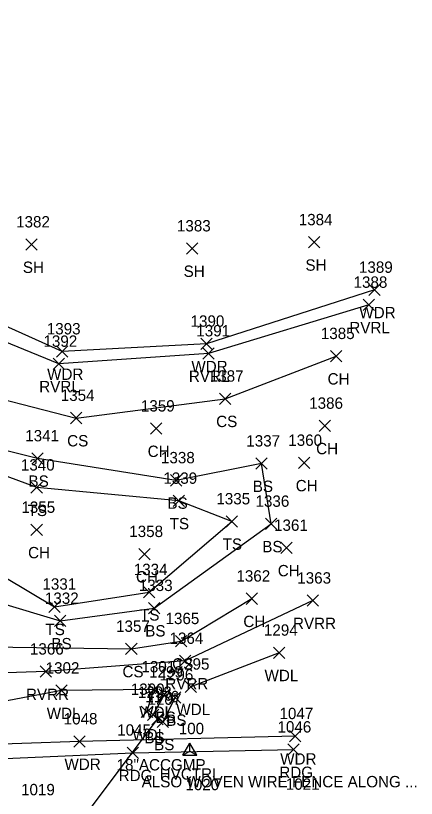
# Model space of a CAD drawing. Extents: x 1621633 to 1624015, y 417863 to 420979.
# Drawn here: x 1622271 to 1622341.5, y 418146.1 to 418283.9 of the extents above; entities that cross this region are included whole.
import ezdxf

# ---------------------------------------------------------------- set-up
doc = ezdxf.new("R2010")
doc.units = 0
for name, color, linetype in [('C_A', 7, 'Continuous'), ('C_I', 7, 'Continuous'), ('CPSM', 7, 'Continuous'), ('D_A', 7, 'Continuous'), ('D_C', 7, 'Continuous'), ('D_I', 7, 'Continuous'), ('D_TIC', 7, 'Continuous'), ('DCP', 7, 'Continuous'), ('L_A', 7, 'Continuous'), ('L_C', 7, 'Continuous'), ('L_I', 7, 'Continuous'), ('L_TIC', 7, 'Continuous'), ('LAWA', 7, 'Continuous'), ('LAWE', 7, 'Continuous'), ('LELB', 7, 'Continuous'), ('P_A', 7, 'Continuous'), ('P_I', 7, 'Continuous'), ('P_TIC', 7, 'Continuous'), ('PEU', 7, 'Continuous')]:
    doc.layers.add(name, color=color, linetype=linetype)

msp = doc.modelspace()

# ---------------------------------------------------------------- linework, layer by layer
at = {"layer": 'CPSM'}
for p, q in [((1622300.42, 418153.71), (1622301.67, 418155.87)), ((1622302.92, 418153.71), (1622301.67, 418155.87)), ((1622301.67, 418154.43), (1622301.67, 418155.87)), ((1622300.42, 418153.71), (1622301.67, 418154.43)), ((1622300.42, 418153.71), (1622302.92, 418153.71)), ((1622301.67, 418154.43), (1622301.67, 418154.43)), ((1622301.67, 418154.43), (1622302.92, 418153.71))]:
    msp.add_line(p, q, dxfattribs=at)
at = {"layer": 'D_TIC'}
for points in [[(1622294.99, 418159.05), (1622296.99, 418161.05)], [(1622296.99, 418159.05), (1622294.99, 418161.05)]]:
    msp.add_lwpolyline(points, dxfattribs=at)
at = {"layer": 'DCP'}
msp.add_lwpolyline([(1622271.54, 418127.58), (1622295.99, 418160.05)], dxfattribs=at)
at = {"layer": 'L_TIC'}
for points in [[(1622272.78, 418242.6), (1622274.78, 418244.6)], [(1622274.78, 418242.6), (1622272.78, 418244.6)], [(1622322.52, 418242.99), (1622324.52, 418244.99)], [(1622324.52, 418242.99), (1622322.52, 418244.99)], [(1622301.08, 418241.9), (1622303.08, 418243.9)], [(1622303.08, 418241.9), (1622301.08, 418243.9)], [(1622333.14, 418234.62), (1622335.14, 418236.62)], [(1622335.14, 418234.62), (1622333.14, 418236.62)], [(1622332.17, 418231.98), (1622334.17, 418233.98)], [(1622334.17, 418231.98), (1622332.17, 418233.98)], [(1622303.57, 418225.13), (1622305.57, 418227.13)], [(1622305.57, 418225.13), (1622303.57, 418227.13)], [(1622278.17, 418223.78), (1622280.17, 418225.78)], [(1622280.17, 418223.78), (1622278.17, 418225.78)], [(1622303.92, 418223.43), (1622305.92, 418225.43)], [(1622305.92, 418223.43), (1622303.92, 418225.43)], [(1622326.42, 418222.96), (1622328.42, 418224.96)], [(1622328.42, 418222.96), (1622326.42, 418224.96)], [(1622277.58, 418221.6), (1622279.58, 418223.6)], [(1622279.58, 418221.6), (1622277.58, 418223.6)], [(1622306.86, 418215.47), (1622308.86, 418217.47)], [(1622308.86, 418215.47), (1622306.86, 418217.47)], [(1622280.63, 418212.07), (1622282.63, 418214.07)], [(1622282.63, 418212.07), (1622280.63, 418214.07)], [(1622294.75, 418210.21), (1622296.75, 418212.21)], [(1622296.75, 418210.21), (1622294.75, 418212.21)], [(1622324.41, 418210.69), (1622326.41, 418212.69)], [(1622326.41, 418210.69), (1622324.41, 418212.69)], [(1622273.82, 418204.96), (1622275.82, 418206.96)], [(1622275.82, 418204.96), (1622273.82, 418206.96)], [(1622313.3, 418204.05), (1622315.3, 418206.05)], [(1622315.3, 418204.05), (1622313.3, 418206.05)], [(1622320.81, 418204.17), (1622322.81, 418206.17)], [(1622322.81, 418204.17), (1622320.81, 418206.17)], [(1622273.7, 418199.82), (1622275.7, 418201.82)], [(1622275.7, 418199.82), (1622273.7, 418201.82)], [(1622298.28, 418201.1), (1622300.28, 418203.1)], [(1622300.28, 418201.1), (1622298.28, 418203.1)], [(1622298.7, 418197.49), (1622300.7, 418199.49)], [(1622300.7, 418197.49), (1622298.7, 418199.49)], [(1622308.03, 418193.87), (1622310.03, 418195.87)], [(1622310.03, 418193.87), (1622308.03, 418195.87)], [(1622314.97, 418193.44), (1622316.97, 418195.44)], [(1622316.97, 418193.44), (1622314.97, 418195.44)], [(1622273.7, 418192.38), (1622275.7, 418194.38)], [(1622275.7, 418192.38), (1622273.7, 418194.38)], [(1622317.65, 418189.21), (1622319.65, 418191.21)], [(1622319.65, 418189.21), (1622317.65, 418191.21)], [(1622292.69, 418188.12), (1622294.69, 418190.12)], [(1622294.69, 418188.12), (1622292.69, 418190.12)], [(1622293.48, 418181.42), (1622295.48, 418183.42)], [(1622295.48, 418181.42), (1622293.48, 418183.42)], [(1622311.6, 418180.28), (1622313.6, 418182.28)], [(1622313.6, 418180.28), (1622311.6, 418182.28)], [(1622322.31, 418179.93), (1622324.31, 418181.93)], [(1622324.31, 418179.93), (1622322.31, 418181.93)], [(1622276.84, 418178.86), (1622278.84, 418180.86)], [(1622278.84, 418178.86), (1622276.84, 418180.86)], [(1622294.37, 418178.62), (1622296.37, 418180.62)], [(1622296.37, 418178.62), (1622294.37, 418180.62)], [(1622277.85, 418176.36), (1622279.85, 418178.36)], [(1622279.85, 418176.36), (1622277.85, 418178.36)], [(1622299.12, 418172.8), (1622301.12, 418174.8)], [(1622301.12, 418172.8), (1622299.12, 418174.8)], [(1622290.36, 418171.44), (1622292.36, 418173.44)], [(1622292.36, 418171.44), (1622290.36, 418173.44)], [(1622316.39, 418170.76), (1622318.39, 418172.76)], [(1622318.39, 418170.76), (1622316.39, 418172.76)], [(1622299.82, 418169.32), (1622301.82, 418171.32)], [(1622301.82, 418169.32), (1622299.82, 418171.32)], [(1622275.31, 418167.44), (1622277.31, 418169.44)], [(1622277.31, 418167.44), (1622275.31, 418169.44)], [(1622278.05, 418164.1), (1622280.05, 418166.1)], [(1622280.05, 418164.1), (1622278.05, 418166.1)], [(1622294.35, 418164.31), (1622296.35, 418166.31)], [(1622296.35, 418164.31), (1622294.35, 418166.31)], [(1622300.86, 418164.79), (1622302.86, 418166.79)], [(1622302.86, 418164.79), (1622300.86, 418166.79)], [(1622296.19, 418163.4), (1622298.19, 418165.4)], [(1622298.19, 418163.4), (1622296.19, 418165.4)], [(1622298.06, 418162.89), (1622300.06, 418164.89)], [(1622300.06, 418162.89), (1622298.06, 418164.89)], [(1622293.12, 418160.35), (1622295.12, 418162.35)], [(1622295.12, 418160.35), (1622293.12, 418162.35)], [(1622294.23, 418159.82), (1622296.23, 418161.82)], [(1622296.23, 418159.82), (1622294.23, 418161.82)], [(1622295.93, 418158.61), (1622297.93, 418160.61)], [(1622297.93, 418158.61), (1622295.93, 418160.61)], [(1622319.21, 418156.08), (1622321.21, 418158.08)], [(1622321.21, 418156.08), (1622319.21, 418158.08)], [(1622281.22, 418155.15), (1622283.22, 418157.15)], [(1622283.22, 418155.15), (1622281.22, 418157.15)]]:
    msp.add_lwpolyline(points, dxfattribs=at)
at = {"layer": 'LAWA'}
for points in [[(1622334.14, 418235.62), (1622304.57, 418226.13), (1622279.17, 418224.78), (1622252.77, 418236.61), (1622231.24, 418254.76), (1622207.28, 418260.97), (1622182.84, 418269.19), (1622160.31, 418273.27), (1622129.81, 418281.16), (1622108.44, 418283.87), (1622096.55, 418277.43), (1622071.98, 418274.52), (1622045.71, 418270.54), (1622021.3, 418265.82)], [(1622320.21, 418157.08), (1622282.22, 418156.15), (1622251.71, 418155.08), (1622223.6, 418155.09), (1622209.11, 418155.31), (1622180.88, 418152.89), (1622152.12, 418150.87), (1622117.37, 418144.74), (1622094.14, 418141.69), (1622062.96, 418134.28), (1622030.01, 418125.89), (1622002.09, 418113.22), (1622001.94, 418118.19), (1622004.41, 418142.61), (1621992.55, 418166.21), (1621982.92, 418190.96), (1621974.22, 418213.57), (1621987.21, 418225.09), (1622016.71, 418238.58), (1622052.18, 418242.59)], [(1622294.12, 418161.35), (1622295.35, 418165.31), (1622279.05, 418165.1), (1622262.62, 418162.03), (1622241.27, 418162.89), (1622220.84, 418170.43), (1622210.97, 418182.32), (1622187.59, 418203.03), (1622170.53, 418217.1), (1622143.74, 418224.16), (1622117.62, 418234.62), (1622098.7, 418232.3), (1622072.64, 418230.63)], [(1622317.39, 418171.76), (1622301.86, 418165.79)]]:
    msp.add_lwpolyline(points, dxfattribs=at)
at = {"layer": 'LAWE'}
for points in [[(1622333.17, 418232.98), (1622304.92, 418224.43), (1622278.58, 418222.6), (1622250.59, 418234.06), (1622231.09, 418250.9), (1622207.09, 418257.63), (1622185.14, 418265.61), (1622157.85, 418271.29), (1622128.42, 418279.11), (1622109.18, 418281.03), (1622103.42, 418276.53), (1622081.07, 418269.59), (1622054.89, 418266.85), (1622024.68, 418262.78), (1621999.35, 418261.34), (1621980.1, 418259.35), (1621959.54, 418247.53), (1621949.11, 418230.91), (1621945.67, 418206.62), (1621950.84, 418182.3), (1621958.69, 418157.04), (1621962.92, 418133.77), (1621970.23, 418110.89)], [(1622323.31, 418180.93), (1622300.82, 418170.32), (1622276.31, 418168.44), (1622241.72, 418167.29), (1622221.82, 418173.51), (1622205.88, 418194.82), (1622185.97, 418220.63), (1622162.23, 418235.42), (1622129.82, 418241.7), (1622106.38, 418246.35), (1622101.43, 418250.25), (1622073.09, 418248.58), (1622043.82, 418244.16), (1622014.93, 418241.31), (1621989.87, 418234.25), (1621972.68, 418220.99), (1621964.49, 418204.33), (1621969.88, 418176.14), (1621978.91, 418154.62), (1621984.37, 418139.62), (1621989.94, 418122.86), (1621991.15, 418115.14)]]:
    msp.add_lwpolyline(points, dxfattribs=at)
at = {"layer": 'LELB'}
for points in [[(1622307.86, 418216.47), (1622327.42, 418223.96)], [(1622260.66, 418218.46), (1622281.63, 418213.07), (1622307.86, 418216.47)], [(1622238.27, 418203.47), (1622256.73, 418184.01), (1622278.85, 418177.36), (1622295.37, 418179.62), (1622315.97, 418194.44), (1622314.3, 418205.05), (1622299.28, 418202.1), (1622274.82, 418205.96), (1622252.2, 418211.57), (1622241.76, 418213.02), (1622238, 418208.35)], [(1622241.77, 418205.67), (1622260.31, 418190.29), (1622277.84, 418179.86), (1622294.48, 418182.42), (1622309.03, 418194.87), (1622299.7, 418198.49), (1622274.7, 418200.82), (1622252.19, 418209.16), (1622242.75, 418211.1)], [(1622300.12, 418173.8), (1622312.6, 418181.28)], [(1622262.12, 418172.89), (1622291.36, 418172.44), (1622300.12, 418173.8)], [(1622299.06, 418163.89), (1622296.93, 418159.61), (1622295.23, 418160.82), (1622297.19, 418164.4)]]:
    msp.add_lwpolyline(points, dxfattribs=at)
at = {"layer": 'P_TIC'}
for points in [[(1622290.64, 418153.17), (1622292.64, 418155.17)], [(1622292.64, 418153.17), (1622290.64, 418155.17)], [(1622318.92, 418153.72), (1622320.92, 418155.72)], [(1622320.92, 418153.72), (1622318.92, 418155.72)]]:
    msp.add_lwpolyline(points, dxfattribs=at)
at = {"layer": 'PEU'}
msp.add_lwpolyline([(1622170.97, 418148.68), (1622202.2, 418150.62), (1622230.95, 418151.66), (1622261.16, 418152.81), (1622291.64, 418154.17), (1622319.92, 418154.72)], dxfattribs=at)

# ---------------------------------------------------------------- texts
at = {"layer": 'C_A'}
msp.add_text('HVCTRL', height=2, dxfattribs=at).set_placement((1622296.36, 418149.43))
at = {"layer": 'C_I'}
msp.add_text('100', height=2, dxfattribs=at).set_placement((1622299.71, 418157.43))
at = {"layer": 'D_A'}
msp.add_text('P', height=2, dxfattribs=at).set_placement((1622295.37, 418155.05))
at = {"layer": 'D_C'}
msp.add_text('18"ACCGMP', height=2, dxfattribs=at).set_placement((1622288.77, 418151.05))
at = {"layer": 'D_I'}
msp.add_text('1176', height=2, dxfattribs=at).set_placement((1622293.81, 418163.05))
at = {"layer": 'L_A'}
for s, p in [('SH', (1622272.27, 418238.6)), ('SH', (1622322.01, 418238.99)), ('SH', (1622300.57, 418237.9)), ('WDR', (1622331.5, 418230.62)), ('RVRL', (1622329.74, 418227.98)), ('WDR', (1622301.93, 418221.13)), ('WDR', (1622276.54, 418219.78)), ('RVRL', (1622301.49, 418219.43)), ('CH', (1622325.91, 418218.96)), ('RVRL', (1622275.15, 418217.6)), ('CS', (1622306.3, 418211.47)), ('CS', (1622280.07, 418208.07)), ('CH', (1622323.9, 418206.69)), ('CH', (1622294.24, 418206.21)), ('BS', (1622273.26, 418200.96)), ('BS', (1622312.74, 418200.05)), ('CH', (1622320.3, 418200.17)), ('BS', (1622297.72, 418197.1)), ('TS', (1622273.11, 418195.82)), ('TS', (1622298.11, 418193.49)), ('TS', (1622307.44, 418189.87)), ('BS', (1622314.41, 418189.44)), ('CH', (1622273.19, 418188.38)), ('CH', (1622317.14, 418185.21)), ('CH', (1622292.18, 418184.12)), ('TS', (1622292.89, 418177.42)), ('CH', (1622311.08, 418176.28)), ('RVRR', (1622319.82, 418175.93)), ('TS', (1622276.25, 418174.86)), ('BS', (1622293.81, 418174.62)), ('BS', (1622277.29, 418172.36)), ('CS', (1622298.56, 418168.8)), ('CS', (1622289.8, 418167.44)), ('WDL', (1622314.81, 418166.76)), ('RVRR', (1622297.33, 418165.32)), ('RVRR', (1622272.82, 418163.44)), ('WDL', (1622276.47, 418160.1)), ('WDL', (1622292.76, 418160.31)), ('WDL', (1622299.28, 418160.79)), ('BS', (1622295.63, 418159.4)), ('BS', (1622297.5, 418158.89)), ('WDL', (1622291.54, 418156.35)), ('BS', (1622293.67, 418155.82)), ('BS', (1622295.37, 418154.61)), ('WDR', (1622317.57, 418152.08)), ('WDR', (1622279.59, 418151.15))]:
    msp.add_text(s, height=2, dxfattribs=at).set_placement(p)
at = {"layer": 'L_C'}
msp.add_text('ALSO WOVEN WIRE FENCE ALONG ...', height=2, dxfattribs=at).set_placement((1622293.18, 418148.08))
at = {"layer": 'L_I'}
for s, p in [('1382', (1622271.08, 418246.6)), ('1384', (1622320.83, 418246.99)), ('1383', (1622299.39, 418245.9)), ('1389', (1622331.43, 418238.62)), ('1388', (1622330.48, 418235.98)), ('1390', (1622301.79, 418229.13)), ('1393', (1622276.48, 418227.78)), ('1391', (1622302.8, 418227.43)), ('1385', (1622324.72, 418226.96)), ('1392', (1622275.89, 418225.6)), ('1387', (1622305.17, 418219.47)), ('1354', (1622278.94, 418216.07)), ('1359', (1622293.05, 418214.21)), ('1386', (1622322.67, 418214.69)), ('1341', (1622272.69, 418208.96)), ('1337', (1622311.6, 418208.05)), ('1360', (1622318.99, 418208.17)), ('1338', (1622296.58, 418205.1)), ('1340', (1622271.92, 418203.82)), ('1339', (1622297, 418201.49)), ('1335', (1622306.33, 418197.87)), ('1336', (1622313.22, 418197.44)), ('1355', (1622272.01, 418196.38)), ('1361', (1622316.48, 418193.21)), ('1358', (1622291, 418192.12)), ('1334', (1622291.79, 418185.42)), ('1362', (1622309.86, 418184.28)), ('1363', (1622320.57, 418183.93)), ('1331', (1622275.71, 418182.86)), ('1333', (1622292.68, 418182.62)), ('1332', (1622276.15, 418180.36)), ('1365', (1622297.38, 418176.8)), ('1357', (1622288.67, 418175.44)), ('1294', (1622314.7, 418174.76)), ('1364', (1622298.08, 418173.32)), ('1366', (1622273.51, 418171.44)), ('1302', (1622276.28, 418168.1)), ('1301', (1622293.14, 418168.31)), ('1295', (1622299.16, 418168.79)), ('1299', (1622294.49, 418167.4)), ('1296', (1622296.32, 418166.89)), ('1300', (1622291.26, 418164.35)), ('1298', (1622292.53, 418163.82)), ('1297', (1622294.23, 418162.61)), ('1047', (1622317.44, 418160.08)), ('1048', (1622279.45, 418159.15))]:
    msp.add_text(s, height=2, dxfattribs=at).set_placement(p)
at = {"layer": 'P_A'}
for p in [(1622289.13, 418149.17), (1622317.41, 418149.72)]:
    msp.add_text('RDG', height=2, dxfattribs=at).set_placement(p)
at = {"layer": 'P_I'}
for s, p in [('1045', (1622288.87, 418157.17)), ('1046', (1622317.09, 418157.72)), ('1020', (1622300.88, 418147.57)), ('1021', (1622318.55, 418147.65)), ('1019', (1622271.95, 418146.68))]:
    msp.add_text(s, height=2, dxfattribs=at).set_placement(p)

doc.saveas('drawing.dxf')
